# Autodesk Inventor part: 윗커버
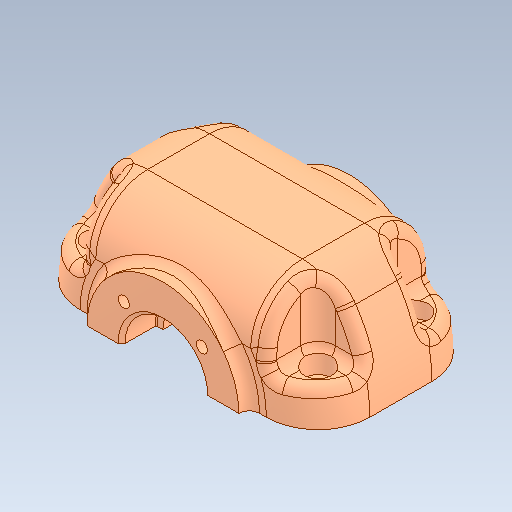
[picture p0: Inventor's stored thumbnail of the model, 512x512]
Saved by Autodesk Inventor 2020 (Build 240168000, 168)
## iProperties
Created: 2024-07
Part Number: 윗커버
Material: 일반
Document SubType Name: Modeling
Designer: oem
Density: 1 g/cm^3
Appearance: 기본값
Mass: 64.3454 g
Surface Area: 167.327 cm^2
Volume: 64.3454 cm^3
Sending System: Autodesk Inventor 2025
Preprocessor: ST-DEVELOPER v20
Author: jhkim
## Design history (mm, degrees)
feature "솔리드1"
node "솔리드2"
